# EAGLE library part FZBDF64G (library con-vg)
CONNECTOR female, 64 pins, type G, rows FDBZ, grid 5.08 mm
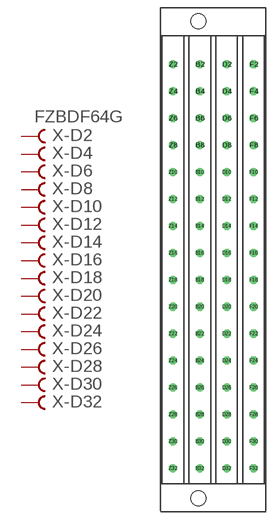
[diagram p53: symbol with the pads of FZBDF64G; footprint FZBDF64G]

Designator prefix X; gates -D2=FVAL -D4=FEM -D6=FEM -D8=FEM -D10=FEM -D12=FEM -D14=FEM -D16=FEM -D18=FEM -D20=FEM -D22=FEM -D24=FEM -D26=FEM -D28=FEM -D30=FEM -D32=FEM -B2=FVAL -B4=FEM -B6=FEM -B8=FEM -B10=FEM -B12=FEM -B14=FEM -B16=FEM -B18=FEM -B20=FEM -B22=FEM -B24=FEM -B26=FEM -B28=FEM -B30=FEM -B32=FEM -Z2=FVAL -Z4=FEM -Z6=FEM -Z8=FEM -Z10=FEM -Z12=FEM -Z14=FEM -Z16=FEM -Z18=FEM -Z20=FEM -Z22=FEM -Z24=FEM -Z26=FEM -Z28=FEM -Z30=FEM -Z32=FEM -F2=FVAL -F4=FEM -F6=FEM -F8=FEM -F10=FEM -F12=FEM -F14=FEM -F16=FEM -F18=FEM -F20=FEM -F22=FEM -F24=FEM -F26=FEM -F28=FEM -F30=FEM -F32=FEM

## FZBDF64G  [FZBDF64G]
B2  -B2:B  pas
B4  -B4:B  pas
B6  -B6:B  pas
B8  -B8:B  pas
B10  -B10:B  pas
B12  -B12:B  pas
B14  -B14:B  pas
B16  -B16:B  pas
B18  -B18:B  pas
B20  -B20:B  pas
B22  -B22:B  pas
B24  -B24:B  pas
B26  -B26:B  pas
B28  -B28:B  pas
B30  -B30:B  pas
B32  -B32:B  pas
D2  -D2:B  pas
D4  -D4:B  pas
D6  -D6:B  pas
D8  -D8:B  pas
D10  -D10:B  pas
D12  -D12:B  pas
D14  -D14:B  pas
D16  -D16:B  pas
D18  -D18:B  pas
D20  -D20:B  pas
D22  -D22:B  pas
D24  -D24:B  pas
D26  -D26:B  pas
D28  -D28:B  pas
D30  -D30:B  pas
D32  -D32:B  pas
F2  -F2:B  pas
F4  -F4:B  pas
F6  -F6:B  pas
F8  -F8:B  pas
F10  -F10:B  pas
F12  -F12:B  pas
F14  -F14:B  pas
F16  -F16:B  pas
F18  -F18:B  pas
F20  -F20:B  pas
F22  -F22:B  pas
F24  -F24:B  pas
F26  -F26:B  pas
F28  -F28:B  pas
F30  -F30:B  pas
F32  -F32:B  pas
Z2  -Z2:B  pas
Z4  -Z4:B  pas
Z6  -Z6:B  pas
Z8  -Z8:B  pas
Z10  -Z10:B  pas
Z12  -Z12:B  pas
Z14  -Z14:B  pas
Z16  -Z16:B  pas
Z18  -Z18:B  pas
Z20  -Z20:B  pas
Z22  -Z22:B  pas
Z24  -Z24:B  pas
Z26  -Z26:B  pas
Z28  -Z28:B  pas
Z30  -Z30:B  pas
Z32  -Z32:B  pas

## Footprint FZBDF64G (pad centres in mm)
CONNECTOR female, 64 pins, type G, rows FDBZ, grid 5.08 mm
drill 1.016 octagon: B2 0,36.855; B4 0,31.775; B6 0,26.695; B8 0,21.615; B10 0,16.535; B12 0,11.455; B14 0,6.375; B16 0,1.295; B18 0,-3.785; B20 0,-8.865; B22 0,-13.945; B24 0,-19.025; B26 0,-24.105; B28 0,-29.185; B30 0,-34.265; B32 0,-39.345; D2 5.08,36.855; D4 5.08,31.775; D6 5.08,26.695; D8 5.08,21.615; D10 5.08,16.535; D12 5.08,11.455; D14 5.08,6.375; D16 5.08,1.295; D18 5.08,-3.785; D20 5.08,-8.865; D22 5.08,-13.945; D24 5.08,-19.025; D26 5.08,-24.105; D28 5.08,-29.185; D30 5.08,-34.265; D32 5.08,-39.345; F2 10.16,36.855; F4 10.16,31.775; F6 10.16,26.695; F8 10.16,21.615; F10 10.16,16.535; F12 10.16,11.455; F14 10.16,6.375; F16 10.16,1.295; F18 10.16,-3.785; F20 10.16,-8.865; F22 10.16,-13.945; F24 10.16,-19.025; F26 10.16,-24.105; F28 10.16,-29.185; F30 10.16,-34.265; F32 10.16,-39.345; Z2 -5.08,36.855; Z4 -5.08,31.775; Z6 -5.08,26.695; Z8 -5.08,21.615; Z10 -5.08,16.535; Z12 -5.08,11.455; Z14 -5.08,6.375; Z16 -5.08,1.295; Z18 -5.08,-3.785; Z20 -5.08,-8.865; Z22 -5.08,-13.945; Z24 -5.08,-19.025; Z26 -5.08,-24.105; Z28 -5.08,-29.185; Z30 -5.08,-34.265; Z32 -5.08,-39.345
hole 2.794 at -0.305,44.983
hole 2.794 at -0.305,-44.983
